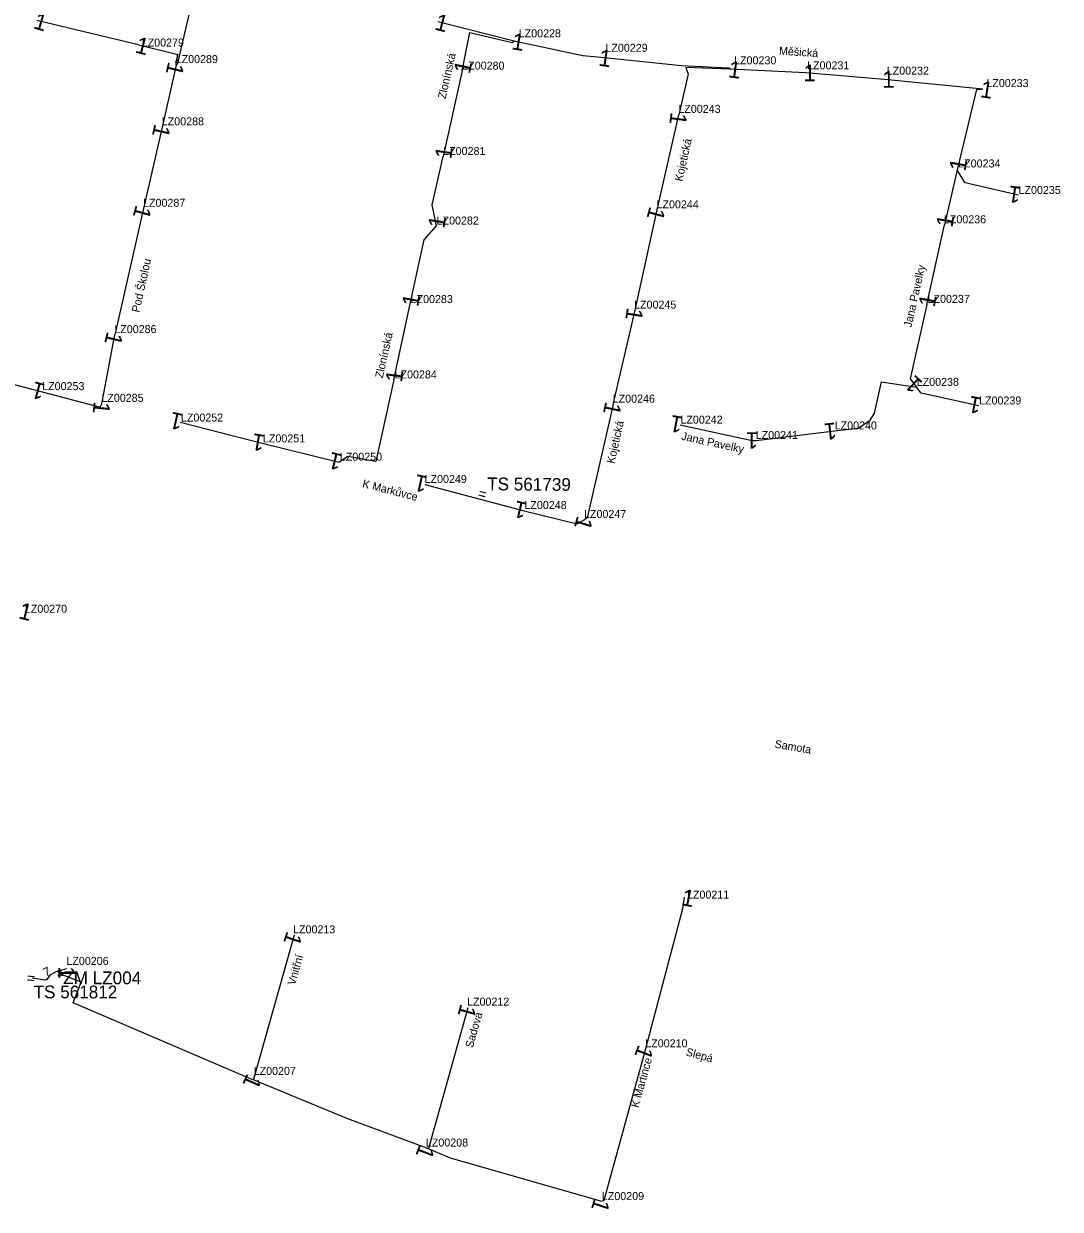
# Model space of a CAD drawing. Extents: x -736540 to -735418, y -1033000 to -1031598.
# Drawn here: x -735742.1 to -735418, y -1032331.3 to -1031960.8 of the extents above; entities that cross this region are included whole.
import ezdxf

# ---------------------------------------------------------------- set-up
doc = ezdxf.new("R2010")
doc.units = 0
for name, color, linetype in [('ftf_2010', 7, 'Continuous'), ('ftf_2060', 7, 'Continuous'), ('ftf_3010', 7, 'Continuous'), ('ftf_3010_ftf_3010_gtda_3015_gtda_3015_1', 7, 'Continuous'), ('ftf_3150', 7, 'Continuous'), ('ftf_3150_ftf_3150_gtda_3155_gtda_3155_1', 7, 'Continuous'), ('ftf_3160', 7, 'Continuous'), ('ftf_3160_ftf_3160_gtda_3165_gtda_3165_1', 7, 'Continuous'), ('ftf_3170', 7, 'Continuous'), ('ftf_nu', 7, 'Continuous')]:
    doc.layers.add(name, color=color, linetype=linetype)

msp = doc.modelspace()

# ---------------------------------------------------------------- linework, layer by layer
at = {"layer": 'ftf_2010'}
for points in [[(-735704.95, -1031871.47), (-735703.88, -1031872.24), (-735701.31, -1031874.26), (-735688.46, -1031888.4), (-735675.6, -1031902.54), (-735685.91, -1031938.23), (-735694.04, -1031973.11), (-735694.47, -1031973.74)], [(-735706.21, -1031967.39), (-735738.01, -1031959.86)], [(-735588.76, -1031966.29), (-735612.61, -1031960.22)], [(-735605.04, -1031975.54), (-735602.63, -1031963.58), (-735589.35, -1031966.7), (-735588.76, -1031966.29)], [(-735561.58, -1031971.42), (-735567.29, -1031970.85), (-735588.76, -1031966.29)], [(-735706.21, -1031967.39), (-735694.25, -1031970.33), (-735693.95, -1031970.46), (-735694.59, -1031973.11), (-735694.47, -1031973.74)], [(-735694.47, -1031973.74), (-735698.78, -1031993.12)], [(-735521.06, -1031975.03), (-735521.58, -1031974.68), (-735536.43, -1031973.93), (-735561.58, -1031971.42)], [(-735521.06, -1031975.03), (-735521.32, -1031975.03), (-735535.1, -1031974.45), (-735534.37, -1031976.56), (-735537.27, -1031989.24)], [(-735605.04, -1031975.54), (-735610.94, -1032002.29)], [(-735497.66, -1031976.19), (-735521.06, -1031975.03)], [(-735473.01, -1031978.2), (-735497.66, -1031976.19)], [(-735442.24, -1031981.24), (-735473.01, -1031978.2)], [(-735442.24, -1031981.24), (-735443.08, -1031981.48), (-735444.2, -1031981.38), (-735450.13, -1032006.06)], [(-735544.02, -1032019), (-735537.27, -1031989.24)], [(-735698.78, -1031993.12), (-735704.66, -1032018.56)], [(-735613.07, -1032023.94), (-735614.43, -1032017.46), (-735610.94, -1032002.29)], [(-735450.13, -1032006.06), (-735454.2, -1032023.66)], [(-735431.05, -1032014.4), (-735447.71, -1032010.57), (-735450.01, -1032006.94), (-735450.13, -1032006.06)], [(-735704.66, -1032018.56), (-735713.63, -1032058.02)], [(-735550.96, -1032050.37), (-735544.02, -1032019)], [(-735621.24, -1032048.4), (-735616.9, -1032028.4), (-735613.07, -1032023.94)], [(-735459.74, -1032048.52), (-735454.2, -1032023.66)], [(-735626.37, -1032072.12), (-735621.24, -1032048.4)], [(-735459.74, -1032048.52), (-735464.97, -1032071.75), (-735462.96, -1032074.44)], [(-735557.79, -1032079.84), (-735550.96, -1032050.37)], [(-735717.65, -1032079.56), (-735713.63, -1032058.02)], [(-735756.77, -1032070.54), (-735736.35, -1032075.88)], [(-735626.37, -1032072.12), (-735631.98, -1032097.59), (-735640.81, -1032096.03), (-735643.51, -1032097.87)], [(-735488.58, -1032088.05), (-735481.17, -1032087.19), (-735477.47, -1032084.69), (-735476.12, -1032082.55), (-735473.94, -1032072.75), (-735462.96, -1032074.44)], [(-735443.47, -1032080.21), (-735461.53, -1032076.24), (-735462.96, -1032074.44)], [(-735736.35, -1032075.88), (-735718.47, -1032080.57), (-735718.04, -1032080.39), (-735717.65, -1032079.56)], [(-735557.79, -1032079.84), (-735565.96, -1032115.27), (-735566.66, -1032115.75)], [(-735693.16, -1032085.29), (-735667.52, -1032091.88)], [(-735536.8, -1032086.19), (-735514.34, -1032091.05), (-735513.08, -1032091.06)], [(-735513.08, -1032091.06), (-735488.58, -1032088.05)], [(-735667.52, -1032091.88), (-735643.51, -1032097.87)], [(-735616.72, -1032104.78), (-735585.62, -1032113.06)], [(-735585.62, -1032113.06), (-735569.08, -1032117.11), (-735566.66, -1032115.75)], [(-735535.6, -1032233.77), (-735536.15, -1032237.39), (-735547.66, -1032281.16)], [(-735657.52, -1032245.6), (-735670.11, -1032290.31)], [(-735731.54, -1032256.92), (-735728.64, -1032256.02)], [(-735670.11, -1032290.31), (-735670.47, -1032290.88), (-735726.59, -1032266.76), (-735724.14, -1032260.29), (-735730.61, -1032257.84), (-735731.54, -1032256.92)], [(-735616.06, -1032312.23), (-735615.47, -1032312.2), (-735603.11, -1032268.22)], [(-735547.66, -1032281.16), (-735560.74, -1032328.52), (-735561.29, -1032328.87)], [(-735616.06, -1032312.23), (-735640.75, -1032303.03), (-735670.07, -1032291), (-735670.11, -1032290.31)], [(-735561.29, -1032328.87), (-735608.62, -1032315.32), (-735616.06, -1032312.23)]]:
    msp.add_lwpolyline(points, dxfattribs=at)
at = {"layer": 'ftf_2060'}
msp.add_lwpolyline([(-735731.54, -1032256.92), (-735731.59, -1032256.9), (-735733.97, -1032258.13), (-735734.85, -1032259.46), (-735735.46, -1032259.68), (-735739.45, -1032259.09)], dxfattribs=at)

# ---------------------------------------------------------------- texts
at = {"layer": 'ftf_3010'}
for rotation, p in [(343.5055, (-735739.36, -1031962.17)), (345.2107, (-735613.9, -1031962.57)), (344.8574, (-735707.52, -1031969.73)), (351.0643, (-735589.8, -1031968.76)), (351.8688, (-735562.58, -1031973.9)), (256.5809, (-735696.85, -1031972.5)), (78.1156, (-735602.63, -1031976.71)), (352.7562, (-735522.03, -1031977.53)), (351.1435, (-735443.28, -1031983.71)), (262.6484, (-735539.76, -1031988.26)), (257.2419, (-735701.17, -1031991.92)), (81.9049, (-735608.45, -1032003.3)), (80.2991, (-735447.68, -1032007.14)), (171.7555, (-735430.04, -1032011.92)), (254.3911, (-735706.99, -1032017.24)), (255.131, (-735546.37, -1032017.7)), (80.9604, (-735610.61, -1032024.99)), (80.7397, (-735451.74, -1032024.72)), (79.9278, (-735618.79, -1032049.49)), (79.5274, (-735457.3, -1032049.63)), (260.8464, (-735553.42, -1032049.32)), (256.8931, (-735716.02, -1032056.8)), (82.7137, (-735623.87, -1032073.09)), (136.7654, (-735460.71, -1032072.99)), (164.8237, (-735735.05, -1032073.54)), (169.0925, (-735442.34, -1032077.78)), (264.4481, (-735720.17, -1032078.67)), (258.1357, (-735560.2, -1032078.67)), (167.2237, (-735691.96, -1032082.9)), (169.2933, (-735535.68, -1032083.76)), (185.8801, (-735488.2, -1032085.4)), (170.1087, (-735666.43, -1032089.43)), (180, (-735512.43, -1032088.46)), (166.0499, (-735642.26, -1032095.51)), (167.823, (-735615.54, -1032102.38)), (166.5453, (-735584.39, -1032110.68)), (253.2462, (-735568.97, -1032114.38)), (346.1327, (-735743.99, -1032146.58)), (349.0135, (-735536.73, -1032236.2)), (251.3735, (-735659.77, -1032244.16)), (270, (-735731.24, -1032255.37)), (254.0365, (-735605.43, -1032266.88)), (249.1464, (-735549.86, -1032279.63)), (245.988, (-735672.22, -1032288.66)), (249.2833, (-735618.27, -1032310.71)), (252.0524, (-735563.56, -1032327.45))]:
    msp.add_text('1', height=5.2, rotation=rotation, dxfattribs=at).set_placement(p)
for p in [(-735498.31, -1031978.79), (-735473.66, -1031980.8)]:
    msp.add_text('1', height=5.2, dxfattribs=at).set_placement(p)
at = {"layer": 'ftf_3010_ftf_3010_gtda_3015_gtda_3015_1'}
for s, p in [('LZ00228', (-735587.33, -1031965.07)), ('LZ00279', (-735705.21, -1031967.94)), ('LZ00229', (-735560.22, -1031969.6)), ('LZ00289', (-735694.59, -1031973.11)), ('LZ00280', (-735604.98, -1031975.17)), ('LZ00230', (-735519.98, -1031973.5)), ('LZ00231', (-735497.16, -1031975.07)), ('LZ00232', (-735472.26, -1031976.73)), ('LZ00233', (-735441.12, -1031980.61)), ('LZ00243', (-735537.41, -1031988.68)), ('LZ00288', (-735698.93, -1031992.57)), ('LZ00281', (-735610.94, -1032001.85)), ('LZ00234', (-735449.91, -1032005.73)), ('LZ00235', (-735431.05, -1032014.03)), ('LZ00287', (-735704.79, -1032018.02)), ('LZ00244', (-735544.24, -1032018.51)), ('LZ00282', (-735613, -1032023.57)), ('LZ00236', (-735454.39, -1032023.18)), ('LZ00283', (-735621.13, -1032048.12)), ('LZ00237', (-735459.49, -1032048.05)), ('LZ00286', (-735713.78, -1032057.51)), ('LZ00284', (-735626.14, -1032071.67)), ('LZ00253', (-735736.32, -1032075.32)), ('LZ00238', (-735462.89, -1032074)), ('LZ00285', (-735717.83, -1032078.98)), ('LZ00246', (-735557.95, -1032079.24)), ('LZ00239', (-735443.39, -1032079.8)), ('LZ00252', (-735692.94, -1032085.13)), ('LZ00242', (-735536.77, -1032085.79)), ('LZ00240', (-735488.54, -1032087.6)), ('LZ00251', (-735667.3, -1032091.65)), ('LZ00241', (-735513.23, -1032090.58)), ('LZ00250', (-735643.25, -1032097.37)), ('LZ00249', (-735616.76, -1032104.34)), ('LZ00248', (-735585.54, -1032112.47)), ('LZ00247', (-735566.92, -1032115.27)), ('LZ00270', (-735741.74, -1032144.89)), ('LZ00211', (-735534.71, -1032234.22)), ('LZ00213', (-735657.89, -1032245.08)), ('LZ00206', (-735728.76, -1032254.94)), ('LZ00212', (-735603.48, -1032267.66)), ('LZ00210', (-735547.76, -1032280.69)), ('LZ00207', (-735670.21, -1032289.31)), ('LZ00208', (-735616.35, -1032311.7)), ('LZ00209', (-735561.33, -1032328.43))]:
    msp.add_text(s, height=2.5, dxfattribs=at).set_placement(p)
msp.add_text('LZ00245', height=2.5, rotation=0, dxfattribs=at).set_placement((-735551.25, -1032049.85))
at = {"layer": 'ftf_3150'}
msp.add_text('>', height=2.7, rotation=208.2512, dxfattribs=at).set_placement((-735730.35, -1032256.28))
at = {"layer": 'ftf_3150_ftf_3150_gtda_3155_gtda_3155_1'}
msp.add_text('ZM LZ004', height=4, rotation=359.7917, dxfattribs=at).set_placement((-735729.74, -1032260.93))
at = {"layer": 'ftf_3160'}
for rotation, p in [(346.0269, (-735600.28, -1032109.02)), (354.3131, (-735741.26, -1032260.57))]:
    msp.add_text('=', height=3.3, rotation=rotation, dxfattribs=at).set_placement(p)
at = {"layer": 'ftf_3160_ftf_3160_gtda_3165_gtda_3165_1'}
for s, rotation, p in [('TS 561739', 359.5026, (-735597.21, -1032106.6)), ('TS 561812', 359.9383, (-735739.02, -1032265.38))]:
    msp.add_text(s, height=4, rotation=rotation, dxfattribs=at).set_placement(p)
at = {"layer": 'ftf_3170'}
msp.add_text('7', height=2.7, rotation=26.1415, dxfattribs=at).set_placement((-735735.18, -1032258.73))
at = {"layer": 'ftf_nu'}
for s, rotation, p in [('Zlonínská', 77.1509, (-735610.23, -1031984.46)), ('Měšická', 356.1596, (-735506.01, -1031970.47)), ('Kojetická', 77.2006, (-735536.19, -1032010.25)), ('Pod Školou', 77.4608, (-735705.97, -1032051.19)), ('Jana Pavelky', 77.3004, (-735464.55, -1032055.88)), ('Zlonínská', 77.387, (-735629.84, -1032071.73)), ('Kojetická', 77.2206, (-735557.43, -1032098.44)), ('Jana Pavelky', 347.6641, (-735536.64, -1032090.79)), ('K Markůvce', 345.7013, (-735636.39, -1032105.62)), ('Samota', 350.4787, (-735507.44, -1032187.03)), ('Vnitřní', 74.2251, (-735657.26, -1032261.43)), ('Sadová', 74.3993, (-735601.69, -1032281.03)), ('Slepá', 344.8379, (-735535.25, -1032283.19)), ('K Martince', 74.5677, (-735549.88, -1032299.75))]:
    msp.add_text(s, height=2.5, rotation=rotation, dxfattribs=at).set_placement(p)

doc.saveas('drawing.dxf')
